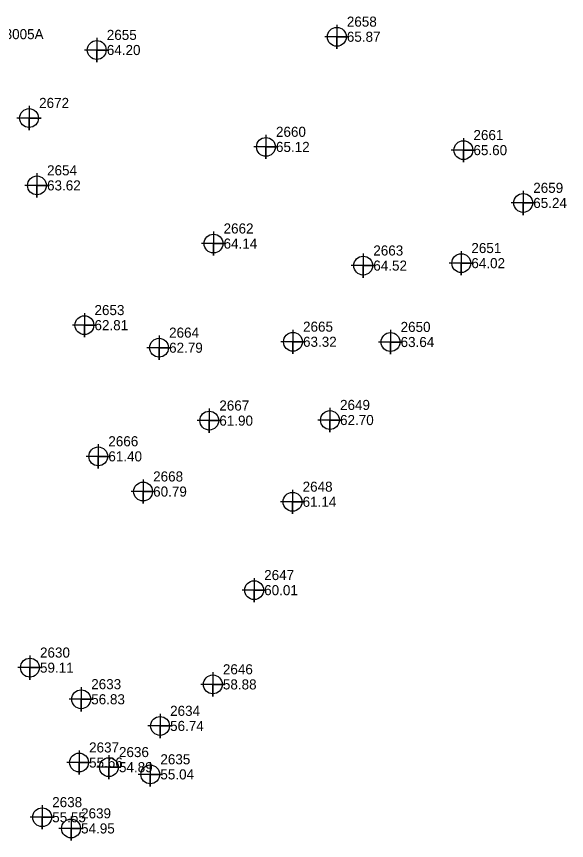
# Model space of a CAD drawing. Extents: x 2062781 to 2066835, y 358981 to 366501.
# Drawn here: x 2066403.1 to 2066539.7, y 365737 to 365941.6 of the extents above; entities that cross this region are included whole.
import ezdxf

# ---------------------------------------------------------------- set-up
doc = ezdxf.new("R2010")
doc.units = 0
for name, color, linetype in [('Exist DTM Regular Point CELL', 7, 'Continuous'), ('Exist DTM Regular Point Cogo Elevation', 7, 'Continuous'), ('Exist DTM Regular Point Cogo Number', 7, 'Continuous'), ('Exist Other Culture Fence Line Cogo Number', 7, 'Continuous'), ('Exist Other Culture Fence Line Cogo Point CELL', 7, 'Continuous'), ('Exist Roads Soil Cogo Comment', 7, 'Continuous')]:
    doc.layers.add(name, color=color, linetype=linetype)

msp = doc.modelspace()

# ---------------------------------------------------------------- linework, layer by layer
at = {"layer": 'Exist DTM Regular Point CELL'}
for points in [[(2066482.63, 365939.51), (2066482.63, 365933.51), (2066482.63, 365936.51), (2066485.63, 365936.51), (2066479.63, 365936.51)], [(2066423.02, 365936.23), (2066423.02, 365930.23), (2066423.02, 365933.23), (2066426.02, 365933.23), (2066420.02, 365933.23)], [(2066465.03, 365912.17), (2066465.03, 365906.17), (2066465.03, 365909.17), (2066468.03, 365909.17), (2066462.03, 365909.17)], [(2066514.07, 365911.37), (2066514.07, 365905.37), (2066514.07, 365908.37), (2066517.07, 365908.37), (2066511.07, 365908.37)], [(2066408.18, 365902.61), (2066408.18, 365896.61), (2066408.18, 365899.61), (2066411.18, 365899.61), (2066405.18, 365899.61)], [(2066528.92, 365898.26), (2066528.92, 365892.26), (2066528.92, 365895.26), (2066531.92, 365895.26), (2066525.92, 365895.26)], [(2066452.02, 365888.17), (2066452.02, 365882.17), (2066452.02, 365885.17), (2066455.02, 365885.17), (2066449.02, 365885.17)], [(2066513.55, 365883.31), (2066513.55, 365877.31), (2066513.55, 365880.31), (2066516.55, 365880.31), (2066510.55, 365880.31)], [(2066489.2, 365882.7), (2066489.2, 365876.7), (2066489.2, 365879.7), (2066492.2, 365879.7), (2066486.2, 365879.7)], [(2066419.96, 365867.91), (2066419.96, 365861.91), (2066419.96, 365864.91), (2066422.96, 365864.91), (2066416.96, 365864.91)], [(2066438.49, 365862.31), (2066438.49, 365856.31), (2066438.49, 365859.31), (2066441.49, 365859.31), (2066435.49, 365859.31)], [(2066471.75, 365863.79), (2066471.75, 365857.79), (2066471.75, 365860.79), (2066474.75, 365860.79), (2066468.75, 365860.79)], [(2066495.98, 365863.73), (2066495.98, 365857.73), (2066495.98, 365860.73), (2066498.98, 365860.73), (2066492.98, 365860.73)], [(2066450.96, 365844.21), (2066450.96, 365838.21), (2066450.96, 365841.21), (2066453.96, 365841.21), (2066447.96, 365841.21)], [(2066480.94, 365844.36), (2066480.94, 365838.36), (2066480.94, 365841.36), (2066483.94, 365841.36), (2066477.94, 365841.36)], [(2066423.4, 365835.34), (2066423.4, 365829.34), (2066423.4, 365832.34), (2066426.4, 365832.34), (2066420.4, 365832.34)], [(2066434.53, 365826.6), (2066434.53, 365820.6), (2066434.53, 365823.6), (2066437.53, 365823.6), (2066431.53, 365823.6)], [(2066471.65, 365824.06), (2066471.65, 365818.06), (2066471.65, 365821.06), (2066474.65, 365821.06), (2066468.65, 365821.06)], [(2066462.1, 365802.12), (2066462.1, 365796.12), (2066462.1, 365799.12), (2066465.1, 365799.12), (2066459.1, 365799.12)], [(2066406.43, 365782.88), (2066406.43, 365776.88), (2066406.43, 365779.88), (2066409.43, 365779.88), (2066403.43, 365779.88)], [(2066451.85, 365778.72), (2066451.85, 365772.72), (2066451.85, 365775.72), (2066454.85, 365775.72), (2066448.85, 365775.72)], [(2066419.15, 365775.03), (2066419.15, 365769.03), (2066419.15, 365772.03), (2066422.15, 365772.03), (2066416.15, 365772.03)], [(2066438.74, 365768.41), (2066438.74, 365762.41), (2066438.74, 365765.41), (2066441.74, 365765.41), (2066435.74, 365765.41)], [(2066418.62, 365759.32), (2066418.62, 365753.32), (2066418.62, 365756.32), (2066421.62, 365756.32), (2066415.62, 365756.32)], [(2066426.04, 365758.17), (2066426.04, 365752.17), (2066426.04, 365755.17), (2066429.04, 365755.17), (2066423.04, 365755.17)], [(2066436.32, 365756.38), (2066436.32, 365750.38), (2066436.32, 365753.38), (2066439.32, 365753.38), (2066433.32, 365753.38)], [(2066409.46, 365745.74), (2066409.46, 365739.74), (2066409.46, 365742.74), (2066412.46, 365742.74), (2066406.46, 365742.74)], [(2066416.63, 365742.96), (2066416.63, 365736.96), (2066416.63, 365739.96), (2066419.63, 365739.96), (2066413.63, 365739.96)]]:
    msp.add_lwpolyline(points, dxfattribs=at)
for centre in [(2066482.63, 365936.51), (2066423.02, 365933.23), (2066465.03, 365909.17), (2066514.07, 365908.37), (2066408.18, 365899.61), (2066528.92, 365895.26), (2066452.02, 365885.17), (2066489.2, 365879.7), (2066513.55, 365880.31), (2066419.96, 365864.91), (2066471.75, 365860.79), (2066495.98, 365860.73), (2066438.49, 365859.31), (2066450.96, 365841.21), (2066480.94, 365841.36), (2066423.4, 365832.34), (2066434.53, 365823.6), (2066471.65, 365821.06), (2066462.1, 365799.12), (2066406.43, 365779.88), (2066451.85, 365775.72), (2066419.15, 365772.03), (2066438.74, 365765.41), (2066418.62, 365756.32), (2066426.04, 365755.17), (2066436.32, 365753.38), (2066409.46, 365742.74), (2066416.63, 365739.96)]:
    msp.add_circle(centre, 2.34, dxfattribs=at)
at = {"layer": 'Exist Other Culture Fence Line Cogo Point CELL'}
msp.add_lwpolyline([(2066406.21, 365919.34), (2066406.21, 365913.34), (2066406.21, 365916.34), (2066409.21, 365916.34), (2066403.21, 365916.34)], dxfattribs=at)
msp.add_circle((2066406.21, 365916.34), 2.34, dxfattribs=at)

# ---------------------------------------------------------------- texts
at = {"layer": 'Exist DTM Regular Point Cogo Elevation'}
for s, p in [('65.87', (2066485.13, 365935.27)), ('64.20', (2066425.52, 365931.98)), ('65.12', (2066467.53, 365907.92)), ('65.60', (2066516.57, 365907.12)), ('63.62', (2066410.68, 365898.36)), ('65.24', (2066531.42, 365894.01)), ('64.14', (2066454.52, 365883.92)), ('64.52', (2066491.7, 365878.45)), ('64.02', (2066516.05, 365879.06)), ('62.81', (2066422.46, 365863.66)), ('62.79', (2066440.99, 365858.06)), ('63.32', (2066474.25, 365859.54)), ('63.64', (2066498.48, 365859.48)), ('61.90', (2066453.46, 365839.96)), ('62.70', (2066483.44, 365840.11)), ('61.40', (2066425.9, 365831.09)), ('60.79', (2066437.03, 365822.35)), ('61.14', (2066474.15, 365819.81)), ('60.01', (2066464.6, 365797.87)), ('59.11', (2066408.93, 365778.63)), ('58.88', (2066454.35, 365774.47)), ('56.83', (2066421.65, 365770.78)), ('56.74', (2066441.24, 365764.16)), ('55.66', (2066421.12, 365755.07)), ('54.89', (2066428.54, 365753.92)), ('55.04', (2066438.82, 365752.13)), ('55.55', (2066411.96, 365741.49)), ('54.95', (2066419.13, 365738.71))]:
    msp.add_text(s, height=2.5, dxfattribs=at).set_placement(p)
at = {"layer": 'Exist DTM Regular Point Cogo Number'}
for s, p in [('2658', (2066485.13, 365939.02)), ('2655', (2066425.52, 365935.73)), ('2660', (2066467.53, 365911.67)), ('2661', (2066516.57, 365910.87)), ('2654', (2066410.68, 365902.11)), ('2659', (2066531.42, 365897.76)), ('2662', (2066454.52, 365887.67)), ('2651', (2066516.05, 365882.81)), ('2663', (2066491.7, 365882.2)), ('2653', (2066422.46, 365867.41)), ('2664', (2066440.99, 365861.81)), ('2665', (2066474.25, 365863.29)), ('2650', (2066498.48, 365863.23)), ('2667', (2066453.46, 365843.71)), ('2649', (2066483.44, 365843.86)), ('2666', (2066425.9, 365834.84)), ('2668', (2066437.03, 365826.1)), ('2648', (2066474.15, 365823.56)), ('2647', (2066464.6, 365801.62)), ('2630', (2066408.93, 365782.38)), ('2646', (2066454.35, 365778.22)), ('2633', (2066421.65, 365774.53)), ('2634', (2066441.24, 365767.91)), ('2637', (2066421.12, 365758.82)), ('2636', (2066428.54, 365757.67)), ('2635', (2066438.82, 365755.88)), ('2638', (2066411.96, 365745.24)), ('2639', (2066419.13, 365742.46))]:
    msp.add_text(s, height=2.5, dxfattribs=at).set_placement(p)
at = {"layer": 'Exist Other Culture Fence Line Cogo Number'}
msp.add_text('2672', height=2.5, dxfattribs=at).set_placement((2066408.71, 365918.84))
at = {"layer": 'Exist Roads Soil Cogo Comment'}
msp.add_text('BL*3005A', height=2.5, dxfattribs=at).set_placement((2066394.76, 365935.92))

doc.saveas('drawing.dxf')
